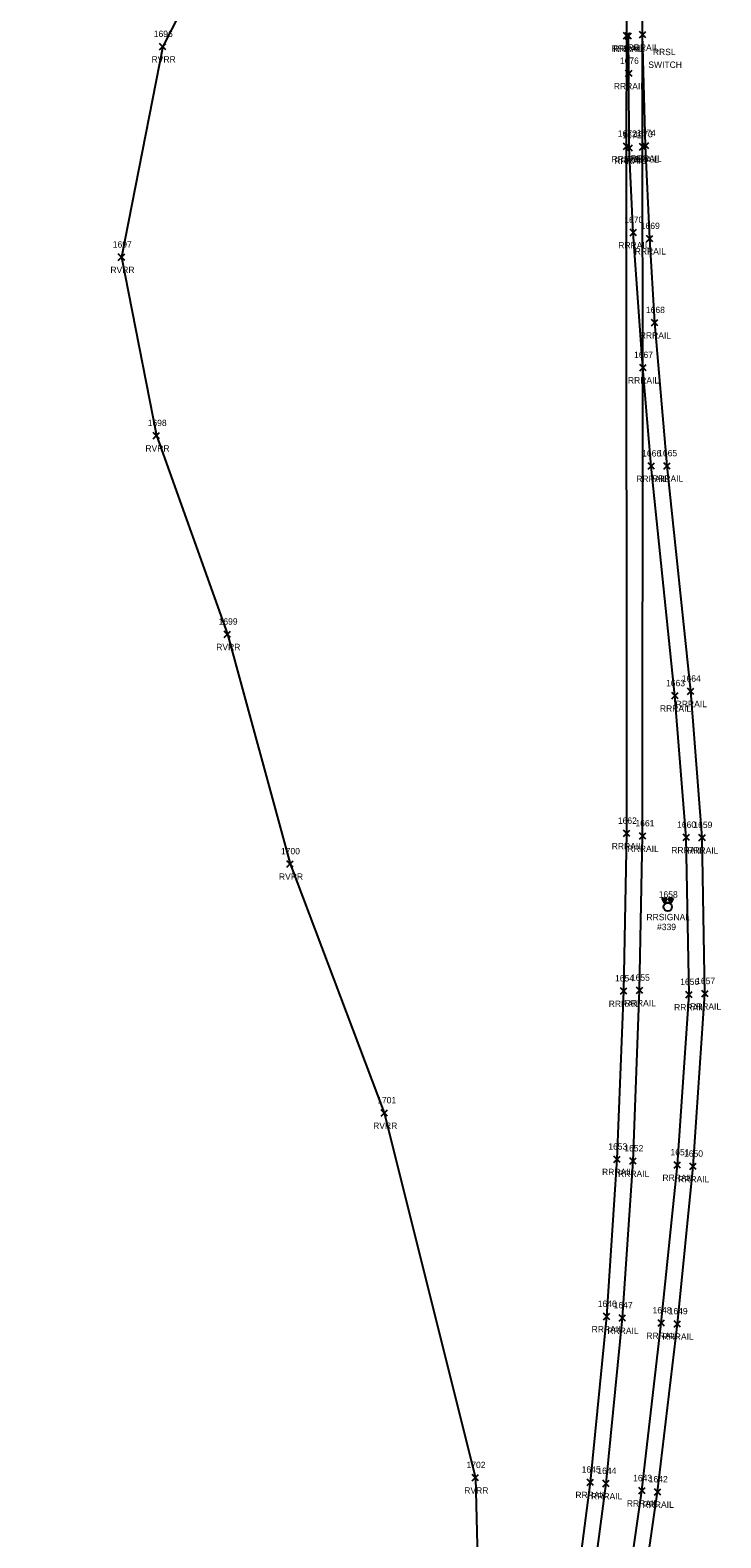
# Model space of a CAD drawing. Extents: x 1767353 to 1772625, y 740790 to 747702.
# Drawn here: x 1771647.4 to 1771864.1, y 745674 to 746146.9 of the extents above; entities that cross this region are included whole.
import ezdxf

# ---------------------------------------------------------------- set-up
doc = ezdxf.new("R2010")
doc.units = 0
for name, color, linetype in [('L_A', 7, 'Continuous'), ('L_I', 7, 'Continuous'), ('L_TIC', 7, 'Continuous'), ('LAWE', 7, 'Continuous'), ('R_A', 7, 'Continuous'), ('R_C', 7, 'Continuous'), ('R_I', 7, 'Continuous'), ('R_TIC', 7, 'Continuous'), ('RR', 7, 'Continuous'), ('TCSH', 7, 'Continuous')]:
    doc.layers.add(name, color=color, linetype=linetype)

msp = doc.modelspace()

# ---------------------------------------------------------------- linework, layer by layer
at = {"layer": 'L_TIC'}
for points in [[(1771687.94, 746140.73), (1771689.94, 746142.73)], [(1771689.94, 746140.73), (1771687.94, 746142.73)], [(1771675.02, 746074.7), (1771677.02, 746076.7)], [(1771677.02, 746074.7), (1771675.02, 746076.7)], [(1771685.98, 746018.71), (1771687.98, 746020.71)], [(1771687.98, 746018.71), (1771685.98, 746020.71)], [(1771708.24, 745956.43), (1771710.24, 745958.43)], [(1771710.24, 745956.43), (1771708.24, 745958.43)], [(1771727.91, 745884.4), (1771729.91, 745886.4)], [(1771729.91, 745884.4), (1771727.91, 745886.4)], [(1771757.46, 745806.28), (1771759.46, 745808.28)], [(1771759.46, 745806.28), (1771757.46, 745808.28)], [(1771786.05, 745691.88), (1771788.05, 745693.88)], [(1771788.05, 745691.88), (1771786.05, 745693.88)]]:
    msp.add_lwpolyline(points, dxfattribs=at)
at = {"layer": 'LAWE'}
msp.add_lwpolyline([(1771704.97, 746173.25), (1771688.94, 746141.73), (1771676.02, 746075.7), (1771686.98, 746019.71), (1771709.24, 745957.43), (1771728.91, 745885.4), (1771758.46, 745807.28), (1771787.05, 745692.88), (1771788.05, 745654.73), (1771784.64, 745590.76), (1771772.87, 745536.44), (1771749.98, 745460.69), (1771712.27, 745353.44), (1771682.71, 745273.4), (1771647.35, 745204.37)], dxfattribs=at)
at = {"layer": 'R_TIC'}
for points in [[(1771833.55, 746144.16), (1771835.55, 746146.16)], [(1771835.55, 746144.16), (1771833.55, 746146.16)], [(1771834.05, 746144.09), (1771836.05, 746146.09)], [(1771836.05, 746144.09), (1771834.05, 746146.09)], [(1771838.5, 746144.44), (1771840.5, 746146.44)], [(1771840.5, 746144.44), (1771838.5, 746146.44)], [(1771838.5, 746144.44), (1771840.5, 746146.44)], [(1771840.5, 746144.44), (1771838.5, 746146.44)], [(1771834.19, 746132.32), (1771836.19, 746134.32)], [(1771836.19, 746132.32), (1771834.19, 746134.32)], [(1771833.47, 746109.44), (1771835.47, 746111.44)], [(1771835.47, 746109.44), (1771833.47, 746111.44)], [(1771834.33, 746108.95), (1771836.33, 746110.95)], [(1771836.33, 746108.95), (1771834.33, 746110.95)], [(1771838.51, 746109.3), (1771840.51, 746111.3)], [(1771840.51, 746109.3), (1771838.51, 746111.3)], [(1771839.43, 746109.66), (1771841.43, 746111.66)], [(1771841.43, 746109.66), (1771839.43, 746111.66)], [(1771835.6, 746082.43), (1771837.6, 746084.43)], [(1771837.6, 746082.43), (1771835.6, 746084.43)], [(1771840.75, 746080.53), (1771842.75, 746082.53)], [(1771842.75, 746080.53), (1771840.75, 746082.53)], [(1771842.34, 746054.16), (1771844.34, 746056.16)], [(1771844.34, 746054.16), (1771842.34, 746056.16)], [(1771838.61, 746040.07), (1771840.61, 746042.07)], [(1771840.61, 746040.07), (1771838.61, 746042.07)], [(1771838.61, 746040.07), (1771840.61, 746042.07)], [(1771840.61, 746040.07), (1771838.61, 746042.07)], [(1771841.22, 746009.17), (1771843.22, 746011.17)], [(1771843.22, 746009.17), (1771841.22, 746011.17)], [(1771846.19, 746009.23), (1771848.19, 746011.23)], [(1771848.19, 746009.23), (1771846.19, 746011.23)], [(1771853.6, 745938.55), (1771855.6, 745940.55)], [(1771855.6, 745938.55), (1771853.6, 745940.55)], [(1771848.66, 745937.12), (1771850.66, 745939.12)], [(1771850.66, 745937.12), (1771848.66, 745939.12)], [(1771833.54, 745893.96), (1771835.54, 745895.96)], [(1771835.54, 745893.96), (1771833.54, 745895.96)], [(1771838.49, 745893.15), (1771840.49, 745895.15)], [(1771840.49, 745893.15), (1771838.49, 745895.15)], [(1771852.23, 745892.71), (1771854.23, 745894.71)], [(1771854.23, 745892.71), (1771852.23, 745894.71)], [(1771857.2, 745892.64), (1771859.2, 745894.64)], [(1771859.2, 745892.64), (1771857.2, 745894.64)], [(1771832.6, 745844.52), (1771834.6, 745846.52)], [(1771834.6, 745844.52), (1771832.6, 745846.52)], [(1771837.58, 745844.74), (1771839.58, 745846.74)], [(1771839.58, 745844.74), (1771837.58, 745846.74)], [(1771853.11, 745843.42), (1771855.11, 745845.42)], [(1771855.11, 745843.42), (1771853.11, 745845.42)], [(1771858.06, 745843.68), (1771860.06, 745845.68)], [(1771860.06, 745843.68), (1771858.06, 745845.68)], [(1771830.49, 745791.77), (1771832.49, 745793.77)], [(1771832.49, 745791.77), (1771830.49, 745793.77)], [(1771835.52, 745791.2), (1771837.52, 745793.2)], [(1771837.52, 745791.2), (1771835.52, 745793.2)], [(1771849.45, 745789.97), (1771851.45, 745791.97)], [(1771851.45, 745789.97), (1771849.45, 745791.97)], [(1771854.35, 745789.53), (1771856.35, 745791.53)], [(1771856.35, 745789.53), (1771854.35, 745791.53)], [(1771827.24, 745742.44), (1771829.24, 745744.44)], [(1771829.24, 745742.44), (1771827.24, 745744.44)], [(1771832.17, 745741.98), (1771834.17, 745743.98)], [(1771834.17, 745741.98), (1771832.17, 745743.98)], [(1771844.39, 745740.39), (1771846.39, 745742.39)], [(1771846.39, 745740.39), (1771844.39, 745742.39)], [(1771849.44, 745740.12), (1771851.44, 745742.12)], [(1771851.44, 745740.12), (1771849.44, 745742.12)], [(1771822.14, 745690.46), (1771824.14, 745692.46)], [(1771824.14, 745690.46), (1771822.14, 745692.46)], [(1771827.06, 745690.06), (1771829.06, 745692.06)], [(1771829.06, 745690.06), (1771827.06, 745692.06)], [(1771838.28, 745687.78), (1771840.28, 745689.78)], [(1771840.28, 745687.78), (1771838.28, 745689.78)], [(1771843.2, 745687.42), (1771845.2, 745689.42)], [(1771845.2, 745687.42), (1771843.2, 745689.42)]]:
    msp.add_lwpolyline(points, dxfattribs=at)
at = {"layer": 'RR'}
for points in [[(1771740.84, 745349.52), (1771757.64, 745396.97), (1771773.69, 745448.06), (1771789.09, 745504.88), (1771800.2, 745552.17), (1771809.61, 745600.04), (1771817.53, 745647.94), (1771823.14, 745691.46), (1771828.24, 745743.44), (1771831.49, 745792.77), (1771833.6, 745845.52), (1771834.54, 745894.96), (1771834.47, 746110.44), (1771834.55, 746145.16), (1771834.86, 746189.21)], [(1771745.41, 745347.65), (1771762.15, 745394.9), (1771778.33, 745446.27), (1771793.75, 745503.08), (1771805.11, 745551.68), (1771814.56, 745599.54), (1771822.33, 745647.61), (1771828.06, 745691.06), (1771833.17, 745742.98), (1771836.52, 745792.2), (1771838.58, 745845.74), (1771839.49, 745894.15), (1771839.61, 746041.07), (1771839.51, 746110.3), (1771839.5, 746145.44), (1771839.69, 746188.68)], [(1771754.35, 745344.38), (1771770.71, 745391.2), (1771787.19, 745443.29), (1771802.99, 745500.53), (1771815.03, 745550.49), (1771824.79, 745597.59), (1771833.03, 745644.73), (1771839.28, 745688.78), (1771845.39, 745741.39), (1771850.45, 745790.97), (1771854.11, 745844.42), (1771853.23, 745893.71), (1771849.66, 745938.12), (1771842.22, 746010.17), (1771839.61, 746041.07), (1771836.6, 746083.43), (1771835.33, 746109.95), (1771835.19, 746133.32), (1771835.05, 746145.09)], [(1771758.88, 745342.98), (1771775.45, 745389.82), (1771792.04, 745442.25), (1771807.62, 745498.6), (1771820, 745550.13), (1771829.56, 745595.84), (1771837.81, 745644.21), (1771844.2, 745688.42), (1771850.44, 745741.12), (1771855.35, 745790.53), (1771859.06, 745844.68), (1771858.2, 745893.64), (1771854.6, 745939.55), (1771847.19, 746010.23), (1771843.34, 746055.16), (1771841.75, 746081.53), (1771840.43, 746110.66), (1771839.5, 746145.44)]]:
    msp.add_lwpolyline(points, dxfattribs=at)
at = {"layer": 'TCSH'}
for p, q in [((1771847.21, 745874.56), (1771845.54, 745874.56)), ((1771845.54, 745874.56), (1771846.31, 745873.23)), ((1771848.47, 745873.23), (1771846.31, 745873.23)), ((1771846.44, 745873.23), (1771847.21, 745874.56)), ((1771849.24, 745874.56), (1771847.58, 745874.56)), ((1771847.58, 745874.56), (1771848.35, 745873.23)), ((1771848.47, 745873.23), (1771849.24, 745874.56)), ((1771847.39, 745871.9), (1771847.39, 745871.9))]:
    msp.add_line(p, q, dxfattribs=at)
for points in [[(1771845.59, 745874.49), (1771847.17, 745874.49)], [(1771845.66, 745874.35), (1771847.09, 745874.35)], [(1771845.74, 745874.22), (1771847.01, 745874.22)], [(1771845.82, 745874.09), (1771846.93, 745874.09)], [(1771845.9, 745873.95), (1771846.86, 745873.95)], [(1771845.97, 745873.82), (1771846.78, 745873.82)], [(1771846.05, 745873.69), (1771846.7, 745873.69)], [(1771846.13, 745873.55), (1771846.63, 745873.55)], [(1771846.2, 745873.42), (1771846.55, 745873.42)], [(1771846.28, 745873.29), (1771846.47, 745873.29)], [(1771847.61, 745874.51), (1771849.22, 745874.51)], [(1771847.68, 745874.38), (1771849.14, 745874.38)], [(1771847.76, 745874.25), (1771849.06, 745874.25)], [(1771847.84, 745874.11), (1771848.99, 745874.11)], [(1771847.91, 745873.98), (1771848.91, 745873.98)], [(1771847.99, 745873.85), (1771848.83, 745873.85)], [(1771848.07, 745873.71), (1771848.75, 745873.71)], [(1771848.14, 745873.58), (1771848.68, 745873.58)], [(1771848.22, 745873.45), (1771848.6, 745873.45)], [(1771848.3, 745873.31), (1771848.52, 745873.31)]]:
    msp.add_lwpolyline(points, dxfattribs=at)
msp.add_circle((1771847.39, 745871.9), 1.33, dxfattribs=at)

# ---------------------------------------------------------------- texts
at = {"layer": 'L_A'}
for p in [(1771685.45, 746136.73), (1771672.53, 746070.7), (1771683.5, 746014.71), (1771705.75, 745952.43), (1771725.42, 745880.4), (1771754.97, 745802.28), (1771783.56, 745687.88)]:
    msp.add_text('RVRR', height=2, dxfattribs=at).set_placement(p)
at = {"layer": 'L_I'}
for s, p in [('1696', (1771686.15, 746144.73)), ('1697', (1771673.28, 746078.7)), ('1698', (1771684.24, 746022.71)), ('1699', (1771706.49, 745960.43)), ('1700', (1771726.05, 745888.4)), ('1701', (1771756.25, 745810.28)), ('1702', (1771784.28, 745695.88))]:
    msp.add_text(s, height=2, dxfattribs=at).set_placement(p)
at = {"layer": 'R_A'}
for s, p in [('RRRAIL', (1771829.84, 746140.16)), ('RRRAIL', (1771830.34, 746140.09)), ('RRRAIL', (1771834.8, 746140.44)), ('RRRAIL', (1771834.8, 746140.44)), ('RRSL', (1771842.74, 746139.06)), ('RRRAIL', (1771830.48, 746128.32)), ('RRRAIL', (1771829.77, 746105.44)), ('RRRAIL', (1771830.62, 746104.95)), ('RRRAIL', (1771834.81, 746105.3)), ('RRRAIL', (1771835.72, 746105.66)), ('RRRAIL', (1771831.89, 746078.43)), ('RRRAIL', (1771837.04, 746076.53)), ('RRRAIL', (1771838.63, 746050.16)), ('RRRAIL', (1771834.9, 746036.07)), ('RRRAIL', (1771834.9, 746036.07)), ('RRRAIL', (1771837.51, 746005.17)), ('RRRAIL', (1771842.48, 746005.23)), ('RRRAIL', (1771844.95, 745933.12)), ('RRRAIL', (1771849.89, 745934.55)), ('RRRAIL', (1771829.83, 745889.96)), ('RRRAIL', (1771834.78, 745889.15)), ('RRRAIL', (1771848.52, 745888.71)), ('RRRAIL', (1771853.49, 745888.64)), ('RRSIGNAL', (1771840.72, 745867.72)), ('RRRAIL', (1771828.89, 745840.52)), ('RRRAIL', (1771833.88, 745840.74)), ('RRRAIL', (1771849.4, 745839.42)), ('RRRAIL', (1771854.35, 745839.68)), ('RRRAIL', (1771826.79, 745787.77)), ('RRRAIL', (1771831.81, 745787.2)), ('RRRAIL', (1771845.74, 745785.97)), ('RRRAIL', (1771850.64, 745785.53)), ('RRRAIL', (1771823.53, 745738.44)), ('RRRAIL', (1771828.46, 745737.98)), ('RRRAIL', (1771840.68, 745736.39)), ('RRRAIL', (1771845.74, 745736.12)), ('RRRAIL', (1771818.43, 745686.46)), ('RRRAIL', (1771823.35, 745686.06)), ('RRRAIL', (1771834.57, 745683.78)), ('RRRAIL', (1771839.49, 745683.42))]:
    msp.add_text(s, height=2, dxfattribs=at).set_placement(p)
at = {"layer": 'R_C'}
for s, p in [('SWITCH', (1771841.31, 746135.06)), ('#339', (1771844.05, 745864.62))]:
    msp.add_text(s, height=2, dxfattribs=at).set_placement(p)
at = {"layer": 'R_I'}
for s, p in [('1676', (1771832.39, 746136.32)), ('1672', (1771831.73, 746113.44)), ('1671', (1771833.16, 746112.95)), ('1673', (1771836.77, 746113.3)), ('1674', (1771837.69, 746113.66)), ('1670', (1771833.77, 746086.43)), ('1669', (1771838.95, 746084.53)), ('1668', (1771840.56, 746058.16)), ('1667', (1771836.82, 746044.07)), ('1667', (1771836.82, 746044.07)), ('1666', (1771839.38, 746013.17)), ('1665', (1771844.4, 746013.23)), ('1664', (1771851.81, 745942.55)), ('1663', (1771846.87, 745941.12)), ('1662', (1771831.75, 745897.96)), ('1661', (1771837.27, 745897.15)), ('1660', (1771850.35, 745896.71)), ('1659', (1771855.45, 745896.64)), ('1658', (1771844.58, 745874.82)), ('1654', (1771830.86, 745848.52)), ('1655', (1771835.84, 745848.74)), ('1656', (1771851.32, 745847.42)), ('1657', (1771856.32, 745847.68)), ('1653', (1771828.75, 745795.77)), ('1652', (1771833.78, 745795.2)), ('1651', (1771848.27, 745793.97)), ('1650', (1771852.52, 745793.53)), ('1646', (1771825.44, 745746.44)), ('1647', (1771830.43, 745745.98)), ('1648', (1771842.65, 745744.39)), ('1649', (1771847.7, 745744.12)), ('1645', (1771820.4, 745694.46)), ('1644', (1771825.32, 745694.06)), ('1643', (1771836.54, 745691.78)), ('1642', (1771841.46, 745691.42))]:
    msp.add_text(s, height=2, dxfattribs=at).set_placement(p)

doc.saveas('drawing.dxf')
